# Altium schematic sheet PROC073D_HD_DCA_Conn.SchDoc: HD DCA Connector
size 431 x 279 mm; Date: Not shown in title block; ApprovedBy: Not shown in title block; CheckedBy: Not shown in title block; Author: Not shown in title block; CompanyName: Not shown in title block; DrawnBy: Charles F. Oladimeji; Engineer: Not shown in title block; Organization: Not shown in title block; Address1: Not shown in title block; Address2: Not shown in title block; Address3: Not shown in title block; Address4: Not shown in title block; DocumentNumber: 10; Revision: Use project parameter SCH_Rev; SheetNumber: 10; SheetTotal: 13; PageSetup: Record=PageOptions¦CenterHorizontal=True¦CenterVertical=True¦PrintScale=1.00¦XCorrection=1.00¦YCorrection=1.00¦PrintKind=0¦BorderSize=5000000¦LeftOffset=0¦BottomOffset=0¦Orientation=2¦PaperLength=1000¦PaperWidth=1000¦Scale=100¦PaperSource=15¦PrintQuality=600¦MediaType=1¦DitherType=10¦PaperKind=Letter¦PrintScaleMode=1
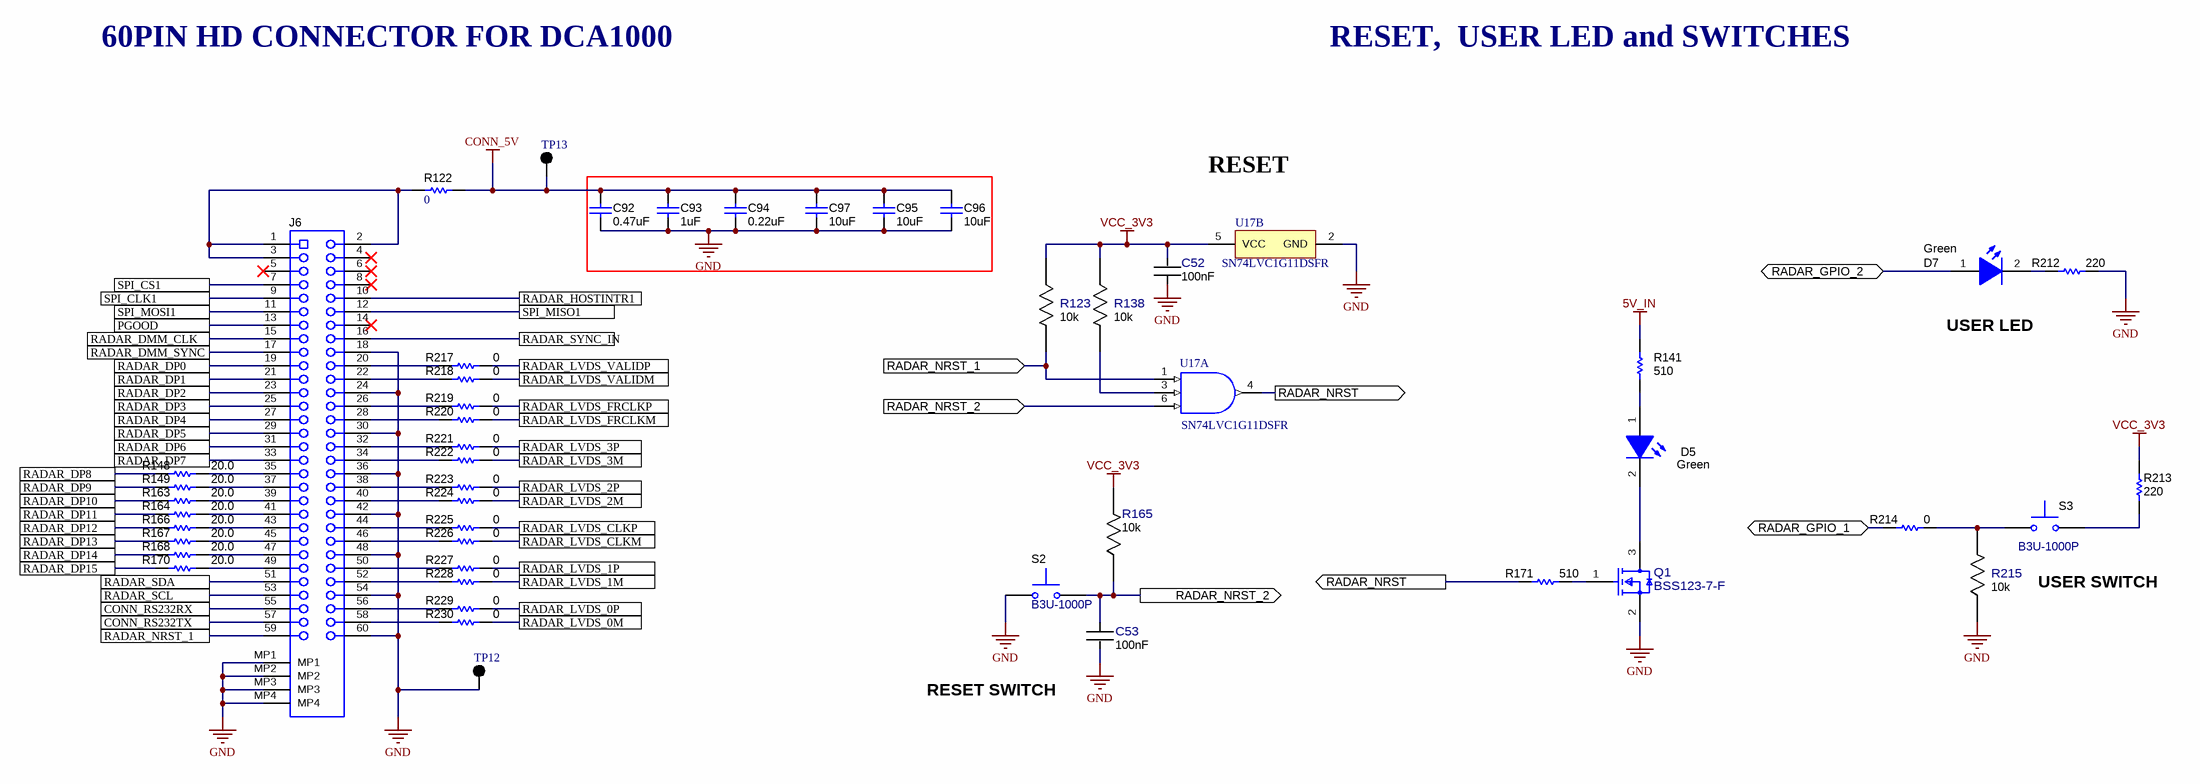
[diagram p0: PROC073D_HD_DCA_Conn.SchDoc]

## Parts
C52  Cap_F: 100nF  [FP-GRM033R6YA104KE14D_0201 (0603 Metric)-IPC_C]  (hidden comment: GRM033R6YA104KE14D)
C53  Cap_F: 100nF  [FP-GRM033R6YA104KE14D_0201 (0603 Metric)-IPC_C]  (hidden comment: GRM033R6YA104KE14D)
C92  ValueDisplayed: 0.47uF  [0402L]  (hidden comment: GCM155C71A474KE36D)
C93  ValueDisplayed: 1uF  [0402L]  (hidden comment: GRT155C81A105KE01D)
C94  ValueDisplayed: 0.22uF  [0402S]  (hidden comment: LMK105B7224KVHF)
C95  ValueDisplayed: 10uF  [0603S]  (hidden comment: GRT188R61A106KE13D)
C96  ValueDisplayed: 10uF  [0603S]  (hidden comment: GRT188R61A106KE13D)
C97  ValueDisplayed: 10uF  [0603S]  (hidden comment: GRT188R61A106KE13D)
D5  Color: Green  [APHHS1005_Green]  (hidden comment: APHHS1005CGCK)
D7  Color: Green  [APHHS1005_Green]  (hidden comment: APHHS1005CGCK)
J6  QSH-030-01-L-D-A  [Samtec_QSH-030-01-X-D-A]  (value not drawn)
Q1  BSS123-7-F  [FP-BSS123-7-F_SOT23-IPC_C]
R122  ValueDisplayed: 0  [0402L]  (hidden comment: ERJ-2GE0R00X)
R123  Res_ohm: 10k  [FP-RR0306P-103-D_0201-IPC_C]  (hidden comment: RR0306P-103-D)
R138  Res_ohm: 10k  [FP-RR0306P-103-D_0201-IPC_C]  (hidden comment: RR0306P-103-D)
R141  value 510  [0201L]  (hidden comment: RC0201JR-07510RL)
R148  ValueDisplayed: 20.0  [0201_033]  (hidden comment: CRCW020120R0FNED)
R149  ValueDisplayed: 20.0  [0201_033]  (hidden comment: CRCW020120R0FNED)
R163  ValueDisplayed: 20.0  [0201_033]  (hidden comment: CRCW020120R0FNED)
R164  ValueDisplayed: 20.0  [0201_033]  (hidden comment: CRCW020120R0FNED)
R165  Res_ohm: 10k  [FP-RR0306P-103-D_0201-IPC_C]  (hidden comment: RR0306P-103-D)
R166  ValueDisplayed: 20.0  [0201_033]  (hidden comment: CRCW020120R0FNED)
R167  ValueDisplayed: 20.0  [0201_033]  (hidden comment: CRCW020120R0FNED)
R168  ValueDisplayed: 20.0  [0201_033]  (hidden comment: CRCW020120R0FNED)
R170  ValueDisplayed: 20.0  [0201_033]  (hidden comment: CRCW020120R0FNED)
R171  value 510  [0201L]  (hidden comment: RC0201JR-07510RL)
R212  value 220  [0201L]  (hidden comment: RC0201JR-07220RL)
R213  value 220  [0201L]  (hidden comment: RC0201JR-07220RL)
R214  Res_ohm: 0  [FP-RC0201JR-070RL_0201 (0603 Metric)-IPC_C]  (hidden comment: RC0201JR-070RL)
R215  Res_ohm: 10k  [FP-RR0306P-103-D_0201-IPC_C]  (hidden comment: RR0306P-103-D)
R217  ValueDisplayed: 0  [0201_Silk]  (hidden comment: CRCW02010000Z0ED)
R218  ValueDisplayed: 0  [0201_Silk]  (hidden comment: CRCW02010000Z0ED)
R219  ValueDisplayed: 0  [0201_Silk]  (hidden comment: CRCW02010000Z0ED)
R220  ValueDisplayed: 0  [0201_Silk]  (hidden comment: CRCW02010000Z0ED)
R221  ValueDisplayed: 0  [0201_Silk]  (hidden comment: CRCW02010000Z0ED)
R222  ValueDisplayed: 0  [0201_Silk]  (hidden comment: CRCW02010000Z0ED)
R223  ValueDisplayed: 0  [0201_Silk]  (hidden comment: CRCW02010000Z0ED)
R224  ValueDisplayed: 0  [0201_Silk]  (hidden comment: CRCW02010000Z0ED)
R225  ValueDisplayed: 0  [0201_Silk]  (hidden comment: CRCW02010000Z0ED)
R226  ValueDisplayed: 0  [0201_Silk]  (hidden comment: CRCW02010000Z0ED)
R227  ValueDisplayed: 0  [0201_Silk]  (hidden comment: CRCW02010000Z0ED)
R228  ValueDisplayed: 0  [0201_Silk]  (hidden comment: CRCW02010000Z0ED)
R229  ValueDisplayed: 0  [0201_Silk]  (hidden comment: CRCW02010000Z0ED)
R230  ValueDisplayed: 0  [0201_Silk]  (hidden comment: CRCW02010000Z0ED)
S2  B3U-1000P  [SW_B3U-1000P]
S3  B3U-1000P  [SW_B3U-1000P]
TP12  5001  [Keystone5001]  (value not drawn)
TP13  5001  [Keystone5001]  (value not drawn)
U17  SN74LVC1G11DSFR  [DSF0006A]  (parts A,B of 2)

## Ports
CONN_RS232RX, CONN_RS232TX, PGOOD, RADAR_DMM_CLK, RADAR_DMM_SYNC, RADAR_DP0, RADAR_DP1, RADAR_DP2, RADAR_DP3, RADAR_DP4, RADAR_DP5, RADAR_DP6, RADAR_DP7, RADAR_DP8, RADAR_DP9, RADAR_DP10, RADAR_DP11, RADAR_DP12, RADAR_DP13, RADAR_DP14, RADAR_DP15, RADAR_GPIO_1 (bidir), RADAR_GPIO_2 (bidir), RADAR_HOSTINTR1, RADAR_LVDS_0M, RADAR_LVDS_0P, RADAR_LVDS_1M, RADAR_LVDS_1P, RADAR_LVDS_2M, RADAR_LVDS_2P, RADAR_LVDS_3M, RADAR_LVDS_3P, RADAR_LVDS_CLKM, RADAR_LVDS_CLKP, RADAR_LVDS_FRCLKM, RADAR_LVDS_FRCLKP, RADAR_LVDS_VALIDM, RADAR_LVDS_VALIDP, RADAR_NRST (out), RADAR_NRST_1, RADAR_NRST_1 (in), RADAR_NRST_2 (in), RADAR_NRST_2 (out), RADAR_SCL, RADAR_SDA, RADAR_SYNC_IN, SPI_CLK1, SPI_CS1, SPI_MISO1, SPI_MOSI1

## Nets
5V_IN: R141.1
CONN_5V: C92.1 C93.1 C94.1 C95.2 C96.2 C97.2 R122.1 TP13.1
GND: C52.1 C53.2 C92.2 C93.2 C94.2 C95.1 C96.1 C97.1 J6.18 J6.24 J6.30 J6.36 J6.42 J6.48 J6.54 J6.60 J6.MP1 J6.MP2 J6.MP3 J6.MP4 Q1.2(S) R212.2 R215.1 S2.2 TP12.1 U17.2(GND)
VCC_3V3: C52.2 R123.1 R138.1 R165.2 R213.2 U17.5(VCC)
CONN_RS232RX: J6.55 ; port CONN_RS232RX
CONN_RS232TX: J6.57 ; port CONN_RS232TX
PGOOD: J6.13 ; port PGOOD
RADAR_DMM_CLK: J6.15 ; port RADAR_DMM_CLK
RADAR_DMM_SYNC: J6.17 ; port RADAR_DMM_SYNC
RADAR_DP0: J6.19 ; port RADAR_DP0
RADAR_DP1: J6.21 ; port RADAR_DP1
RADAR_DP2: J6.23 ; port RADAR_DP2
RADAR_DP3: J6.25 ; port RADAR_DP3
RADAR_DP4: J6.27 ; port RADAR_DP4
RADAR_DP5: J6.29 ; port RADAR_DP5
RADAR_DP6: J6.31 ; port RADAR_DP6
RADAR_DP7: J6.33 ; port RADAR_DP7
RADAR_DP8: R148.1 ; port RADAR_DP8
RADAR_DP9: R149.1 ; port RADAR_DP9
RADAR_DP10: R163.1 ; port RADAR_DP10
RADAR_DP11: R164.1 ; port RADAR_DP11
RADAR_DP12: R166.1 ; port RADAR_DP12
RADAR_DP13: R167.1 ; port RADAR_DP13
RADAR_DP14: R168.1 ; port RADAR_DP14
RADAR_DP15: R170.1 ; port RADAR_DP15
RADAR_GPIO_1: R214.2 ; port RADAR_GPIO_1
RADAR_GPIO_2: D7.1(A) ; port RADAR_GPIO_2
RADAR_HOSTINTR1: J6.10 ; port RADAR_HOSTINTR1
RADAR_LVDS_0M: R230.2 ; port RADAR_LVDS_0M
RADAR_LVDS_0P: R229.2 ; port RADAR_LVDS_0P
RADAR_LVDS_1M: R228.2 ; port RADAR_LVDS_1M
RADAR_LVDS_1P: R227.2 ; port RADAR_LVDS_1P
RADAR_LVDS_2M: R224.2 ; port RADAR_LVDS_2M
RADAR_LVDS_2P: R223.2 ; port RADAR_LVDS_2P
RADAR_LVDS_3M: R222.2 ; port RADAR_LVDS_3M
RADAR_LVDS_3P: R221.2 ; port RADAR_LVDS_3P
RADAR_LVDS_CLKM: R226.2 ; port RADAR_LVDS_CLKM
RADAR_LVDS_CLKP: R225.2 ; port RADAR_LVDS_CLKP
RADAR_LVDS_FRCLKM: R220.2 ; port RADAR_LVDS_FRCLKM
RADAR_LVDS_FRCLKP: R219.2 ; port RADAR_LVDS_FRCLKP
RADAR_LVDS_VALIDM: R218.2 ; port RADAR_LVDS_VALIDM
RADAR_LVDS_VALIDP: R217.2 ; port RADAR_LVDS_VALIDP
RADAR_NRST: R171.1 U17.4(Y) ; port RADAR_NRST
RADAR_NRST_1: J6.59 R123.2 U17.1(A) ; port RADAR_NRST_1
RADAR_NRST_2: C53.1 R165.1 S2.1 U17.6(C) ; port RADAR_NRST_2
RADAR_SCL: J6.53 ; port RADAR_SCL
RADAR_SDA: J6.51 ; port RADAR_SDA
RADAR_SYNC_IN: J6.16 ; port RADAR_SYNC_IN
SPI_CLK1: J6.9 ; port SPI_CLK1
SPI_CS1: J6.7 ; port SPI_CS1
SPI_MISO1: J6.12 ; port SPI_MISO1
SPI_MOSI1: J6.11 ; port SPI_MOSI1
NetD5_1: D5.1(A) R141.2
NetD5_2: D5.2(K) Q1.3(D)
NetD7_2: D7.2(K) R212.1
NetJ6_1: J6.1 J6.2 J6.3 R122.2
NetJ6_20: J6.20 R217.1
NetJ6_22: J6.22 R218.1
NetJ6_26: J6.26 R219.1
NetJ6_28: J6.28 R220.1
NetJ6_32: J6.32 R221.1
NetJ6_34: J6.34 R222.1
NetJ6_35: J6.35 R148.2
NetJ6_37: J6.37 R149.2
NetJ6_38: J6.38 R223.1
NetJ6_39: J6.39 R163.2
NetJ6_40: J6.40 R224.1
NetJ6_41: J6.41 R164.2
NetJ6_43: J6.43 R166.2
NetJ6_44: J6.44 R225.1
NetJ6_45: J6.45 R167.2
NetJ6_46: J6.46 R226.1
NetJ6_47: J6.47 R168.2
NetJ6_49: J6.49 R170.2
NetJ6_50: J6.50 R227.1
NetJ6_52: J6.52 R228.1
NetJ6_56: J6.56 R229.1
NetJ6_58: J6.58 R230.1
NetQ1_1: Q1.1(G) R171.2
NetR138_2: R138.2 U17.3(B)
NetR213_1: R213.1 S3.2
NetR214_1: R214.1 R215.2 S3.1

Not connected (* = marked no-connect by the designer): J6 4* 5* 6* 8* 14*

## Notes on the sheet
- 60PIN HD CONNECTOR FOR DCA1000
- RESET,  USER LED and SWITCHES
- RESET
- USER LED
- (near S3) USER SWITCH
- RESET SWITCH

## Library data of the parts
C52 C53 = CMP-0086440-1: Cap Ceramic 0.1uF 35V X5R 10% Pad SMD 0201 85C T/R; Manufacturer: Murata Electronics North America; AEC Qualified: No; SizeZ_mm: 0.33mm; Symbol Name: SYM-GRM033R6YA104KE14D; TempCo: 15%
C92 = CMP-0064967-2: CAP, CERM, 0.47 uF, 10 V,+/- 10%, X7S, 0402; Manufacturer: MuRata; Polarized: N; Value: 0.47uF; U/M: EA; Cap_F: 470nF; Value1: Unknown; VDC_V: 10V; TaMin_C: -55°C; TaMax_C: 125°C; Cap_Case: 0402; SizeArea_mm2: 0.5; SizeAreaWB_mm2: 3; SizeX_mm: 1; SizeZ_mm: 0.6; AEC Category: Q200
C93 = CMP-0006272-2: CAP, CERM, 1 uF, 10 V, +/- 10%, X6S, 0402; Manufacturer: TDK; Polarized: N; Value: 1uF; U/M: EA; Cap_F: 1µF; Value1: Unknown; VDC_V: 16V; TempCo: X5R; TaMin_C: -55°C; TaMax_C: 85°C; Cap_Case: 0402; SizeArea_mm2: 0.5; SizeAreaWB_mm2: 3; SizeX_mm: 1; SizeZ_mm: 0.6; AEC Category: Q200
C94 = CMP-0006262-2: CAP, CERM, 0.22 uF, 10 V, +/- 10%, X7R, 0402; Manufacturer: TDK; Polarized: N; Value: 0.22uF; U/M: EA; Cap_F: 220nF; Value1: Unknown; VDC_V: 10V; TempCo: X5R; TaMin_C: -55°C; TaMax_C: 85°C; Cap_Case: 0402; SizeArea_mm2: 0.5; SizeAreaWB_mm2: 3; SizeX_mm: 1; SizeZ_mm: 0.6; AEC Category: Q200
C95-C97 = CMP-0007497-5: CAP, CERM, 10 uF, 10 V, +/- 10%, X5R, 0603; Manufacturer: MuRata; Polarized: N; Value: 10uF; U/M: EA; Cap_F: 10µF; Tolerance_%: 20%; Value1: Unknown; VDC_V: 10V; TempCo: X7R; TaMin_C: -55°C; TaMax_C: 125°C; Cap_Case: 0603; SizeArea_mm2: 1.28; SizeAreaWB_mm2: 4.68; SizeX_mm: 1.6; SizeY_mm: 0.8; SizeZ_mm: 1; AEC Category: Q200
D5 D7 = CMP-0067682-2: LED, Green, SMD; Manufacturer: Kingbright; Angle: 120.0; Power_TotalModule: 75mW; SizeZ_mm: 0.6; Vf_V: 2.1V; Vr_V: 5V; Io_A: 20mA; Ir_A: 10µA; SizeArea_mm2: 0.5; SizeAreaWB_mm2: 3.0; SizeX_mm: 1.0; Tjmax_C: 85°C; Value1: 0.075W
J6 = CMP-0075524-1: Receptacle, 0.5 mm, 30x2, Gold, TH; Manufacturer: Samtec; Pitch_mm: 0.5; Gender: Female; Green_REACh: Passed; CT: False; Shrouded: N; RowSpacing_mm: 5.73; Green_Lifecycle: Active; Row_Count: 2
Q1 = CMP-0087176-1: MOSFET N-CH 100V 170MA SOT23-3; Manufacturer: Diodes Incorporated; AEC Qualified: No; ChMode: False; Rdson45_ohm: 6; SizeZ_mm: 1.1mm; Vgs_V: 20V
R122 = CMP-0026992-3: RES, 0, 5%, 0.1 W, AEC-Q200 Grade 0, 0402; Manufacturer: Panasonic; Power_W: 100mW; TempCo: 600 ppm/C; Value_Code: 0000; Value: 0; EIA_Code: E24; SizeX_mm: 1; SizeY_mm: 0.5; SizeZ_mm: 0.6; Value2: 0.1W; AEC Qualified: Y; VDC_V: 50V; AEC Category: Q200; SizeAreaWB_mm2: 3
R123 R138 R165 R215 = CMP-0088002-1: 10 kOhms ±0.5% 0.05W, 1/20W Chip Resistor 0201 (0603 Metric)  Thin Film; Manufacturer: Susumu; AEC Qualified: No; Power_W: 50mW; SizeZ_mm: 0.26mm; Symbol Name: SYM-RR0306P-103-D; TempCo: 25ppm/°C; VDC_V: 15V
R141 R171 = CMP-0027137-1: RES, 510, 5%, 0.05 W, 0201; Manufacturer: Yageo America; AEC Category: Q200; AEC Qualified: N; EIA_Code: E24; Power_W: 50mW; SizeArea_mm2: 0.18; SizeX_mm: 0.6; SizeY_mm: 0.3; SizeZ_mm: 0.26; TempCo: 200 ppm/C; U/M: EA; Value2: 0.05W; Value_Code: 510R; VDC_V: 25V
R148 R149 R163 R164 R166-R168 R170 = CMP-0078192-2: RES, 20.0, 1%, 0.05 W, 0201; Manufacturer: Vishay-Dale; Value_Code: 20R0; SizeArea_mm2: 0.18; AEC Qualified: N; AEC Category: Q200; Res_ohm: 20; Value: 20.0; SizeZ_mm: 0.33; EIA_Code: E96; TempCo: 200 ppm/C; Power_W: 50mW; VDC_V: 30V; SizeY_mm: 0.3; Value2: 0.05W; SizeX_mm: 0.6
R212 R213 = CMP-0027072-1: RES, 220, 5%, 0.05 W, 0201; Manufacturer: Yageo America; AEC Category: Q200; AEC Qualified: N; EIA_Code: E24; Power_W: 50mW; SizeArea_mm2: 0.18; SizeX_mm: 0.6; SizeY_mm: 0.3; SizeZ_mm: 0.26; TempCo: 200 ppm/C; U/M: EA; Value2: 0.05W; Value_Code: 220R; VDC_V: 25V
R214 = CMP-0086442-2: RES SMD 0 OHM JUMPER 1/20W 0201; Manufacturer: Yageo; AEC Qualified: No; Power_W: 50mW; SizeZ_mm: 0.26mm; TempCo: 200ppm/°C; Tolerance_%: 5%; VDC_V: 25V
R217-R230 = CMP-0027008-4: RES, 0, 5%, 0.05 W, 0201; Manufacturer: Vishay-Dale; Power_W: 50mW; TempCo: ppm/C; Value_Code: 0000; Value: 0; EIA_Code: E24; SizeX_mm: 0.6; SizeY_mm: 0.3; SizeZ_mm: 0.26; Value2: 0.05W; SizeArea_mm2: 0.18; AEC Qualified: N; AEC Category: Q200
S2 S3 = CMP-0002150-2: SWITCH TACTILE SPST-NO 0.05A 12V; Manufacturer: Omron Electronic Components; CurrentRating_mA: 50A; PositionCount: 1; SwitchFunction: Off-Mom
TP12 TP13 = CMP-0055138-1: Test Point, Miniature, Black, TH; Manufacturer: Keystone; CNHeader: FALSE; Green_Lifecycle: Active; Green_REACh: Passed; ContactFinish: Silver; CT: TRUE
U17 = CMP-0051215-4: Single 3-Input Positive-AND Gate, DSF0006A, LARGE T&R; Manufacturer: Texas Instruments; Output Type: CMOS; Bits(#): 1; Input Type: CMOS/TTL; Technology Family: LVC; Schmitt Trigger: No; VCC(Max)(V): 5.5; Gate Type: AND; Rating: Catalog; Output Drive (IOL/IOH)(Max)(mA): 32/-32; ICC @ Nom Voltage(Max)(mA): 0.01; VCC(Min)(V): 1.65; F @ Nom Voltage(Max)(Mhz): 150; Logic: True; Voltage(Nom)(V): 1.8,2.5,3.3,5; tpd @ Nom Voltage(Max)(ns): 20,7.8,6.2,4.6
